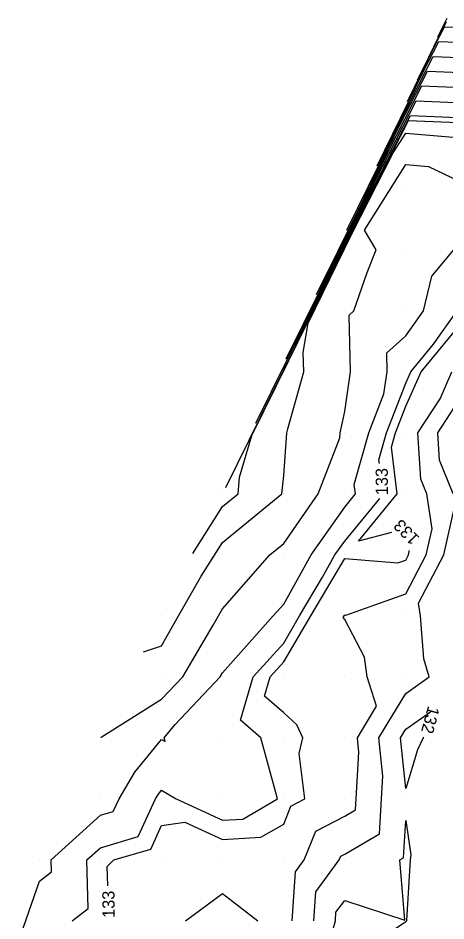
# Model space of a CAD drawing. Extents: x 2354170 to 2357230, y 866100 to 868290.
# Drawn here: x 2354206.4 to 2354276.5, y 867750 to 867898 of the extents above; entities that cross this region are included whole.
import ezdxf

# ---------------------------------------------------------------- set-up
doc = ezdxf.new("R2010")
doc.units = 0
for name, color, linetype in [('Default', 7, 'Continuous'), ('DTM Contours Major', 7, 'Continuous'), ('DTM Contours Minor', 7, 'Continuous'), ('DTM Contours Minor Text', 7, 'Continuous'), ('Exist DTM QL2 LIDAR Elevation Point', 7, 'Continuous')]:
    doc.layers.add(name, color=color, linetype=linetype)

msp = doc.modelspace()

# ---------------------------------------------------------------- linework, layer by layer
at = {"layer": 'Default'}
for points in [[(2354275.21, 867894.95), (2354275.98, 867896.51), (2354276.73, 867898.05)], [(2354270.24, 867884.39), (2354272.55, 867889.07), (2354274.79, 867893.64), (2354276.31, 867896.62), (2354278.13, 867896.54), (2354280.74, 867895.27), (2354301.71, 867886.64), (2354302.66, 867886.52), (2354304.54, 867885.55), (2354305.08, 867885.29), (2354329.26, 867872.85), (2354330.58, 867871.9), (2354331.55, 867871.72), (2354348.52, 867863.4), (2354349.23, 867862.75), (2354349.89, 867862.86), (2354354.45, 867860.94)], [(2354265.28, 867873.84), (2354269.12, 867881.62), (2354272.84, 867889.23), (2354275.39, 867894.19), (2354278.4, 867894.07), (2354282.75, 867891.94), (2354299.15, 867885.2), (2354302.37, 867884.77), (2354304.05, 867883.9), (2354305.78, 867883.08), (2354326.46, 867872.44), (2354329.26, 867870.42), (2354331.33, 867870.03), (2354345.84, 867862.91), (2354347.96, 867861), (2354349.9, 867861.31), (2354361.17, 867856.57), (2354362.11, 867854.06), (2354363.74, 867854.76), (2354374.33, 867847.6), (2354386.56, 867841.13), (2354387.65, 867838.7), (2354389.99, 867833.06), (2354392.88, 867835.2)], [(2354260.32, 867863.29), (2354265.69, 867874.17), (2354270.9, 867884.82), (2354274.46, 867891.77), (2354278.68, 867891.59), (2354284.76, 867888.62), (2354296.59, 867883.76), (2354302.09, 867883.02), (2354303.57, 867882.26), (2354306.49, 867880.87), (2354323.67, 867872.03), (2354327.94, 867868.95), (2354331.1, 867868.35), (2354343.17, 867862.43), (2354346.68, 867859.24), (2354349.91, 867859.77), (2354359.64, 867855.67), (2354361.57, 867850.52), (2354364.93, 867851.94), (2354373.5, 867846.15), (2354383.39, 867840.92), (2354385.47, 867836.24), (2354389.98, 867825.42), (2354395.53, 867829.52)], [(2354255.35, 867852.74), (2354262.26, 867866.72), (2354268.95, 867880.41), (2354273.53, 867889.34), (2354278.95, 867889.11), (2354286.77, 867885.29), (2354294.02, 867882.31), (2354301.8, 867881.28), (2354303.08, 867880.62), (2354307.2, 867878.65), (2354320.87, 867871.62), (2354326.62, 867867.47), (2354327.45, 867867.31)], [(2354250.39, 867842.18), (2354258.83, 867859.27), (2354267.01, 867876), (2354272.6, 867886.91), (2354279.23, 867886.64)], [(2354245.42, 867831.63), (2354255.4, 867851.83), (2354265.06, 867871.59), (2354271.67, 867884.49), (2354279.5, 867884.16)], [(2354240.46, 867821.08), (2354251.97, 867844.38), (2354263.12, 867867.18), (2354270.74, 867882.06), (2354279.78, 867881.69), (2354283.19, 867880.02), (2354285.94, 867875.99), (2354289.96, 867874.83), (2354292.87, 867877.11), (2354299.13, 867876.28)], [(2354227.01, 867794.12), (2354229.96, 867795.11), (2354232.73, 867800.02), (2354236.46, 867806.52), (2354239.96, 867812.04), (2354249.68, 867820.02), (2354249.96, 867823.06), (2354250.49, 867830.02), (2354250.64, 867830.69), (2354253.27, 867840.02), (2354253.16, 867843.21), (2354253.96, 867848.02), (2354261.17, 867862.77), (2354267.92, 867875.93), (2354269.96, 867879.2), (2354278.41, 867878.47)], [(2354220, 867780.1), (2354220.07, 867780.13), (2354229.96, 867786.37), (2354233.43, 867790.02), (2354238.43, 867798.49), (2354239.29, 867800.02), (2354239.96, 867801.19), (2354247.69, 867810.02), (2354249.96, 867811.91), (2354255.64, 867820.02), (2354259.14, 867829.2), (2354259.2, 867830.02), (2354259.96, 867833.54), (2354260.93, 867840.02), (2354260.68, 867849.31), (2354261.47, 867850.02), (2354263.63, 867856.35), (2354265.12, 867860.02), (2354263.21, 867863.27), (2354269.96, 867874.05), (2354273.68, 867873.73), (2354279.96, 867870.7)], [(2354267.62, 867813.7), (2354262.22, 867812.27), (2354268.57, 867820.02), (2354267.61, 867827.67), (2354268.28, 867830.02), (2354269.96, 867834.42), (2354272.47, 867840.02), (2354279.96, 867849.14), (2354280.71, 867850.02), (2354283.18, 867856.81), (2354282.1, 867860.02), (2354289.96, 867865.33), (2354298.42, 867868.48), (2354298.6, 867860.02), (2354299.27, 867850.71), (2354298.82, 867850.02), (2354299.96, 867848.37), (2354300.35, 867847.83)], [(2354206.44, 867746.5), (2354209.96, 867756.57), (2354211.9, 867758.08), (2354211.86, 867760.02), (2354219.96, 867767.34), (2354222.03, 867767.95), (2354222.98, 867770.02), (2354225.56, 867774.42), (2354229.96, 867779.79), (2354230.54, 867779.44), (2354230.38, 867780.02), (2354232.17, 867782.22), (2354239.57, 867790.02), (2354239.96, 867790.69), (2354248.24, 867800.02), (2354249.96, 867801.97), (2354254.47, 867810.02), (2354259.96, 867817.87), (2354261.73, 867820.02), (2354261.53, 867821.59), (2354263.93, 867830.02), (2354266.39, 867836.45), (2354266.92, 867840.02), (2354266.84, 867843.14), (2354269.96, 867845.95), (2354272.85, 867850.02), (2354274.26, 867855.73), (2354277.87, 867860.02)], [(2354251.36, 867750.02), (2354251.89, 867758.09), (2354253.31, 867760.02), (2354255.25, 867764.74), (2354259.96, 867767.22), (2354261.73, 867768.26), (2354261.83, 867770.02), (2354262.28, 867777.7), (2354262.04, 867780.02), (2354265.17, 867785.23), (2354263.62, 867790.02), (2354263.2, 867793.25), (2354259.96, 867799.46), (2354259.72, 867799.77), (2354259.86, 867800.02), (2354259.96, 867800.19), (2354260.12, 867800.18), (2354269.96, 867803.64), (2354273.31, 867810.02), (2354274.27, 867814.33), (2354273.4, 867820.02), (2354272.41, 867822.47), (2354271.96, 867830.02), (2354275.58, 867835.64), (2354277.54, 867840.02)], [(2354277.71, 867820.02), (2354275.48, 867825.54), (2354275.21, 867830.02), (2354279.96, 867837.39)], [(2354254.89, 867750.02), (2354255.21, 867754.77), (2354259.08, 867760.02), (2354259.33, 867760.65), (2354259.96, 867760.98), (2354265.66, 867764.32), (2354266, 867770.02), (2354266.22, 867773.76), (2354265.58, 867780.02), (2354269.96, 867787.33), (2354273.79, 867790.02), (2354272.92, 867792.97), (2354272.37, 867800.02), (2354272.07, 867802.13), (2354276.21, 867810.02), (2354278.01, 867818.07)], [(2354221.15, 867755.76), (2354221.05, 867758.94), (2354222.14, 867760.02), (2354228.19, 867761.79), (2354229.96, 867765.69), (2354233.76, 867766.22), (2354239.96, 867763.4), (2354246.23, 867763.76), (2354249.96, 867765.91), (2354251.16, 867768.82), (2354253.43, 867770.02), (2354252.49, 867777.5), (2354253.08, 867780.02), (2354252.1, 867782.15), (2354249.96, 867784.12), (2354246.8, 867786.86), (2354247.74, 867790.02), (2354249.96, 867792.5), (2354254.4, 867800.02), (2354259.96, 867809.47), (2354268.66, 867808.71), (2354269.96, 867809.17), (2354270.41, 867810.02), (2354270.54, 867810.59), (2354270.51, 867810.78)], [(2354269.96, 867771.74), (2354269.11, 867780.02), (2354269.96, 867781.45), (2354274.01, 867784.3)], [(2354272.87, 867780.17), (2354272.81, 867780.02), (2354271.91, 867778.07), (2354269.96, 867771.74)], [(2354252.88, 867732.94), (2354255.59, 867740.02), (2354256.55, 867743.43), (2354258.43, 867750.02), (2354258.53, 867751.46), (2354259.96, 867753.4), (2354269.83, 867750.15), (2354268.97, 867760.02), (2354269.6, 867760.39), (2354269.96, 867766.5), (2354270.81, 867760.87), (2354270.71, 867760.02), (2354270.06, 867750.11), (2354270.1, 867750.02), (2354270.01, 867749.97), (2354269.96, 867749.85), (2354264.06, 867745.92), (2354266.61, 867740.02), (2354265.94, 867735.99), (2354264.53, 867730.02), (2354263.43, 867726.55), (2354261.45, 867720.02)], [(2354233.87, 867750.02), (2354239.96, 867754.54), (2354245.7, 867750.02)]]:
    msp.add_lwpolyline(points, dxfattribs=at)
at = {"layer": 'DTM Contours Major'}
msp.add_lwpolyline([(2354255.35, 867852.74), (2354262.26, 867866.72), (2354268.95, 867880.41), (2354273.53, 867889.34), (2354278.95, 867889.11), (2354286.77, 867885.29), (2354294.02, 867882.31), (2354301.8, 867881.28), (2354303.08, 867880.62), (2354307.2, 867878.65), (2354320.87, 867871.62), (2354326.62, 867867.47), (2354327.45, 867867.31)], dxfattribs=at)
at = {"layer": 'DTM Contours Minor'}
for points in [[(2354271.9, 867887.91), (2354273.69, 867891.55), (2354275.43, 867895.11), (2354276.62, 867897.43)], [(2354235.09, 867810.28), (2354239.96, 867817.95), (2354242.48, 867820.02), (2354242.74, 867822.8), (2354244.77, 867829.63), (2354250.83, 867841.9), (2354262.47, 867865.71), (2354270.43, 867881.25), (2354279.87, 867880.86)], [(2354265.66, 867825.04), (2354265.58, 867825.64), (2354266.83, 867830.02), (2354269.96, 867838.2), (2354270.77, 867840.02), (2354274.51, 867844.57), (2354278.38, 867850.02)], [(2354215.29, 867750.02), (2354217.91, 867752.07), (2354217.73, 867760.02), (2354219.96, 867762.03), (2354226.14, 867763.84), (2354228.94, 867770.02), (2354229.32, 867770.66), (2354229.96, 867771.44), (2354232.32, 867770.02), (2354239.96, 867766.54), (2354243.25, 867766.73), (2354248.96, 867770.02), (2354248.54, 867771.44), (2354246.23, 867780.02), (2354242.87, 867782.93), (2354244.97, 867790.02), (2354249.96, 867795.59), (2354252.58, 867800.02), (2354256.32, 867806.38), (2354258.36, 867810.02), (2354259.96, 867812.31), (2354265.7, 867819.29)], [(2354269.96, 867771.74), (2354269.11, 867780.02), (2354269.96, 867781.45), (2354274.01, 867784.3)], [(2354272.87, 867780.17), (2354272.81, 867780.02), (2354271.91, 867778.07), (2354269.96, 867771.74)], [(2354252.88, 867732.94), (2354255.59, 867740.02), (2354256.55, 867743.43), (2354258.43, 867750.02), (2354258.53, 867751.46), (2354259.96, 867753.4), (2354269.83, 867750.15), (2354268.97, 867760.02), (2354269.6, 867760.39), (2354269.96, 867766.5), (2354270.81, 867760.87), (2354270.71, 867760.02), (2354270.06, 867750.11), (2354270.1, 867750.02), (2354270.01, 867749.97), (2354269.96, 867749.85), (2354266.92, 867747.82)]]:
    msp.add_lwpolyline(points, dxfattribs=at)
at = {"layer": 'Exist DTM QL2 LIDAR Elevation Point'}
for p, q in [((2354269.96, 867880.02), (2354269.96, 867880.02)), ((2354269.96, 867870.02), (2354269.96, 867870.02)), ((2354259.96, 867860.02), (2354259.96, 867860.02)), ((2354269.96, 867860.02), (2354269.96, 867860.02)), ((2354259.96, 867850.02), (2354259.96, 867850.02)), ((2354269.96, 867850.02), (2354269.96, 867850.02)), ((2354249.96, 867840.02), (2354249.96, 867840.02)), ((2354259.96, 867840.02), (2354259.96, 867840.02)), ((2354269.96, 867840.02), (2354269.96, 867840.02)), ((2354249.96, 867830.02), (2354249.96, 867830.02)), ((2354259.96, 867830.02), (2354259.96, 867830.02)), ((2354269.96, 867830.02), (2354269.96, 867830.02)), ((2354239.96, 867820.02), (2354239.96, 867820.02)), ((2354249.96, 867820.02), (2354249.96, 867820.02)), ((2354259.96, 867820.02), (2354259.96, 867820.02)), ((2354269.96, 867820.02), (2354269.96, 867820.02)), ((2354239.96, 867810.02), (2354239.96, 867810.02)), ((2354249.96, 867810.02), (2354249.96, 867810.02)), ((2354259.96, 867810.02), (2354259.96, 867810.02)), ((2354269.96, 867810.02), (2354269.96, 867810.02)), ((2354229.96, 867800.02), (2354229.96, 867800.02)), ((2354239.96, 867800.02), (2354239.96, 867800.02)), ((2354249.96, 867800.02), (2354249.96, 867800.02)), ((2354259.96, 867800.02), (2354259.96, 867800.02)), ((2354269.96, 867800.02), (2354269.96, 867800.02)), ((2354229.96, 867790.02), (2354229.96, 867790.02)), ((2354239.96, 867790.02), (2354239.96, 867790.02)), ((2354249.96, 867790.02), (2354249.96, 867790.02)), ((2354259.96, 867790.02), (2354259.96, 867790.02)), ((2354269.96, 867790.02), (2354269.96, 867790.02)), ((2354219.96, 867780.02), (2354219.96, 867780.02)), ((2354229.96, 867780.02), (2354229.96, 867780.02)), ((2354239.96, 867780.02), (2354239.96, 867780.02)), ((2354249.96, 867780.02), (2354249.96, 867780.02)), ((2354259.96, 867780.02), (2354259.96, 867780.02)), ((2354269.96, 867780.02), (2354269.96, 867780.02)), ((2354219.96, 867770.02), (2354219.96, 867770.02)), ((2354229.96, 867770.02), (2354229.96, 867770.02)), ((2354239.96, 867770.02), (2354239.96, 867770.02)), ((2354249.96, 867770.02), (2354249.96, 867770.02)), ((2354259.96, 867770.02), (2354259.96, 867770.02)), ((2354269.96, 867770.02), (2354269.96, 867770.02)), ((2354209.96, 867760.02), (2354209.96, 867760.02)), ((2354219.96, 867760.02), (2354219.96, 867760.02)), ((2354229.96, 867760.02), (2354229.96, 867760.02)), ((2354239.96, 867760.02), (2354239.96, 867760.02)), ((2354249.96, 867760.02), (2354249.96, 867760.02)), ((2354259.96, 867760.02), (2354259.96, 867760.02)), ((2354269.96, 867760.02), (2354269.96, 867760.02))]:
    msp.add_line(p, q, dxfattribs=at)

# ---------------------------------------------------------------- texts
at = {"layer": 'Default'}
for s, rotation, p in [('133', 134.6812, (2354272.34, 867812.86)), ('132', 254.6034, (2354273.64, 867785.38)), ('133', 90.6136, (2354222.28, 867750.53))]:
    msp.add_text(s, height=2, rotation=rotation, dxfattribs=at).set_placement(p)
at = {"layer": 'DTM Contours Minor Text'}
for s, rotation, p in [('133', 90.3427, (2354267.05, 867819.82)), ('132', 254.6034, (2354273.64, 867785.38))]:
    msp.add_text(s, height=2, rotation=rotation, dxfattribs=at).set_placement(p)

doc.saveas('drawing.dxf')
